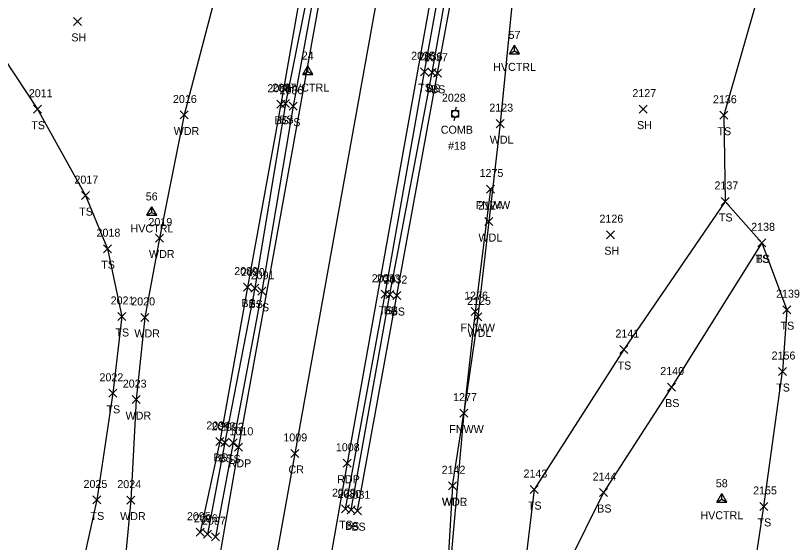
# Model space of a CAD drawing. Extents: x 1754529 to 1755810, y 621660 to 624656.
# Drawn here: x 1755421.2 to 1755616, y 623791.7 to 623923.4 of the extents above; entities that cross this region are included whole.
import ezdxf

# ---------------------------------------------------------------- set-up
doc = ezdxf.new("R2010")
doc.units = 0
for name, color, linetype in [('C_A', 7, 'Continuous'), ('C_I', 7, 'Continuous'), ('CPSM', 7, 'Continuous'), ('L_A', 7, 'Continuous'), ('L_I', 7, 'Continuous'), ('L_TIC', 7, 'Continuous'), ('LAWA', 7, 'Continuous'), ('LELB', 7, 'Continuous'), ('Level 14', 7, 'Continuous'), ('LFNC', 7, 'Continuous'), ('P_A', 7, 'Continuous'), ('P_I', 7, 'Continuous'), ('PET', 7, 'Continuous'), ('PRC', 7, 'Continuous'), ('U_A', 7, 'Continuous'), ('U_C', 7, 'Continuous'), ('U_I', 7, 'Continuous'), ('UP', 7, 'Continuous')]:
    doc.layers.add(name, color=color, linetype=linetype)

msp = doc.modelspace()

# ---------------------------------------------------------------- linework, layer by layer
at = {"layer": 'CPSM'}
for p, q in [((1755544.56, 623913.82), (1755545.81, 623915.99)), ((1755544.56, 623913.82), (1755545.81, 623914.54)), ((1755547.06, 623913.82), (1755545.81, 623915.99)), ((1755545.81, 623914.54), (1755545.81, 623915.99)), ((1755545.81, 623914.54), (1755545.81, 623914.54)), ((1755545.81, 623914.54), (1755547.06, 623913.82)), ((1755544.56, 623913.82), (1755547.06, 623913.82)), ((1755492.9, 623908.64), (1755494.15, 623910.8)), ((1755495.4, 623908.64), (1755494.15, 623910.8)), ((1755494.15, 623909.36), (1755494.15, 623910.8)), ((1755492.9, 623908.64), (1755494.15, 623909.36)), ((1755492.9, 623908.64), (1755495.4, 623908.64)), ((1755494.15, 623909.36), (1755494.15, 623909.36)), ((1755494.15, 623909.36), (1755495.4, 623908.64)), ((1755453.95, 623873.44), (1755455.2, 623875.6)), ((1755456.45, 623873.44), (1755455.2, 623875.6)), ((1755455.2, 623874.16), (1755455.2, 623875.6)), ((1755453.95, 623873.44), (1755455.2, 623874.16)), ((1755453.95, 623873.44), (1755456.45, 623873.44)), ((1755455.2, 623874.16), (1755455.2, 623874.16)), ((1755455.2, 623874.16), (1755456.45, 623873.44)), ((1755596.36, 623801.75), (1755597.61, 623803.92)), ((1755598.86, 623801.75), (1755597.61, 623803.92)), ((1755597.61, 623802.48), (1755597.61, 623803.92)), ((1755596.36, 623801.75), (1755597.61, 623802.48)), ((1755596.36, 623801.75), (1755598.86, 623801.75)), ((1755597.61, 623802.48), (1755597.61, 623802.48)), ((1755597.61, 623802.48), (1755598.86, 623801.75))]:
    msp.add_line(p, q, dxfattribs=at)
at = {"layer": 'L_TIC'}
for points in [[(1755435.6, 623920.91), (1755437.6, 623922.91)], [(1755437.6, 623920.91), (1755435.6, 623922.91)], [(1755522.35, 623908.32), (1755524.35, 623910.32)], [(1755524.35, 623908.32), (1755522.35, 623910.32)], [(1755524.28, 623908.17), (1755526.28, 623910.17)], [(1755526.28, 623908.17), (1755524.28, 623910.17)], [(1755525.55, 623907.94), (1755527.55, 623909.94)], [(1755527.55, 623907.94), (1755525.55, 623909.94)], [(1755425.67, 623898.96), (1755427.67, 623900.96)], [(1755427.67, 623898.96), (1755425.67, 623900.96)], [(1755486.4, 623900.21), (1755488.4, 623902.21)], [(1755488.4, 623900.21), (1755486.4, 623902.21)], [(1755487.64, 623900.37), (1755489.64, 623902.37)], [(1755489.64, 623900.37), (1755487.64, 623902.37)], [(1755489.5, 623899.71), (1755491.5, 623901.71)], [(1755491.5, 623899.71), (1755489.5, 623901.71)], [(1755576.98, 623898.98), (1755578.98, 623900.98)], [(1755578.98, 623898.98), (1755576.98, 623900.98)], [(1755462.31, 623897.52), (1755464.31, 623899.52)], [(1755464.31, 623897.52), (1755462.31, 623899.52)], [(1755597.16, 623897.45), (1755599.16, 623899.45)], [(1755599.16, 623897.45), (1755597.16, 623899.45)], [(1755541.23, 623895.35), (1755543.23, 623897.35)], [(1755543.23, 623895.35), (1755541.23, 623897.35)], [(1755437.63, 623877.37), (1755439.63, 623879.37)], [(1755439.63, 623877.37), (1755437.63, 623879.37)], [(1755538.8, 623879.02), (1755540.8, 623881.02)], [(1755540.8, 623879.02), (1755538.8, 623881.02)], [(1755597.5, 623875.91), (1755599.5, 623877.91)], [(1755599.5, 623875.91), (1755597.5, 623877.91)], [(1755597.5, 623875.91), (1755599.5, 623877.91)], [(1755599.5, 623875.91), (1755597.5, 623877.91)], [(1755538.41, 623870.88), (1755540.41, 623872.88)], [(1755540.41, 623870.88), (1755538.41, 623872.88)], [(1755568.81, 623867.6), (1755570.81, 623869.6)], [(1755570.81, 623867.6), (1755568.81, 623869.6)], [(1755456.13, 623866.77), (1755458.13, 623868.77)], [(1755458.13, 623866.77), (1755456.13, 623868.77)], [(1755606.67, 623865.57), (1755608.67, 623867.57)], [(1755608.67, 623865.57), (1755606.67, 623867.57)], [(1755606.67, 623865.57), (1755608.67, 623867.57)], [(1755608.67, 623865.57), (1755606.67, 623867.57)], [(1755443.15, 623864.1), (1755445.15, 623866.1)], [(1755445.15, 623864.1), (1755443.15, 623866.1)], [(1755478.14, 623854.5), (1755480.14, 623856.5)], [(1755480.14, 623854.5), (1755478.14, 623856.5)], [(1755479.93, 623854.25), (1755481.93, 623856.25)], [(1755481.93, 623854.25), (1755479.93, 623856.25)], [(1755481.67, 623853.46), (1755483.67, 623855.46)], [(1755483.67, 623853.46), (1755481.67, 623855.46)], [(1755512.5, 623852.71), (1755514.5, 623854.71)], [(1755514.5, 623852.71), (1755512.5, 623854.71)], [(1755513.71, 623852.68), (1755515.71, 623854.68)], [(1755515.71, 623852.68), (1755513.71, 623854.68)], [(1755515.45, 623852.4), (1755517.45, 623854.4)], [(1755517.45, 623852.4), (1755515.45, 623854.4)], [(1755535, 623848.38), (1755537, 623850.38)], [(1755537, 623848.38), (1755535, 623850.38)], [(1755612.91, 623848.85), (1755614.91, 623850.85)], [(1755614.91, 623848.85), (1755612.91, 623850.85)], [(1755446.69, 623847.16), (1755448.69, 623849.16)], [(1755448.69, 623847.16), (1755446.69, 623849.16)], [(1755452.48, 623846.93), (1755454.48, 623848.93)], [(1755454.48, 623846.93), (1755452.48, 623848.93)], [(1755535.68, 623847.06), (1755537.68, 623849.06)], [(1755537.68, 623847.06), (1755535.68, 623849.06)], [(1755572.19, 623838.9), (1755574.19, 623840.9)], [(1755574.19, 623838.9), (1755572.19, 623840.9)], [(1755611.83, 623833.4), (1755613.83, 623835.4)], [(1755613.83, 623833.4), (1755611.83, 623835.4)], [(1755611.83, 623833.4), (1755613.83, 623835.4)], [(1755613.83, 623833.4), (1755611.83, 623835.4)], [(1755584.04, 623829.52), (1755586.04, 623831.52)], [(1755586.04, 623829.52), (1755584.04, 623831.52)], [(1755444.46, 623827.96), (1755446.46, 623829.96)], [(1755446.46, 623827.96), (1755444.46, 623829.96)], [(1755450.28, 623826.38), (1755452.28, 623828.38)], [(1755452.28, 623826.38), (1755450.28, 623828.38)], [(1755532.19, 623823), (1755534.19, 623825)], [(1755534.19, 623823), (1755532.19, 623825)], [(1755471.16, 623815.92), (1755473.16, 623817.92)], [(1755473.16, 623815.92), (1755471.16, 623817.92)], [(1755472.47, 623815.7), (1755474.47, 623817.7)], [(1755474.47, 623815.7), (1755472.47, 623817.7)], [(1755474.56, 623815.58), (1755476.56, 623817.58)], [(1755476.56, 623815.58), (1755474.56, 623817.58)], [(1755529.31, 623804.85), (1755531.31, 623806.85)], [(1755531.31, 623804.85), (1755529.31, 623806.85)], [(1755529.31, 623804.85), (1755531.31, 623806.85)], [(1755531.31, 623804.85), (1755529.31, 623806.85)], [(1755549.78, 623803.9), (1755551.78, 623805.9)], [(1755551.78, 623803.9), (1755549.78, 623805.9)], [(1755567.05, 623803.16), (1755569.05, 623805.16)], [(1755569.05, 623803.16), (1755567.05, 623805.16)], [(1755440.47, 623801.31), (1755442.47, 623803.31)], [(1755442.47, 623801.31), (1755440.47, 623803.31)], [(1755448.92, 623801.26), (1755450.92, 623803.26)], [(1755450.92, 623801.26), (1755448.92, 623803.26)], [(1755607.16, 623799.69), (1755609.16, 623801.69)], [(1755609.16, 623799.69), (1755607.16, 623801.69)], [(1755502.59, 623799.12), (1755504.59, 623801.12)], [(1755504.59, 623799.12), (1755502.59, 623801.12)], [(1755504.03, 623798.81), (1755506.03, 623800.81)], [(1755506.03, 623798.81), (1755504.03, 623800.81)], [(1755505.63, 623798.61), (1755507.63, 623800.61)], [(1755507.63, 623798.61), (1755505.63, 623800.61)], [(1755466.3, 623793.24), (1755468.3, 623795.24)], [(1755468.3, 623793.24), (1755466.3, 623795.24)], [(1755468.09, 623792.73), (1755470.09, 623794.73)], [(1755470.09, 623792.73), (1755468.09, 623794.73)], [(1755470.08, 623792.12), (1755472.08, 623794.12)], [(1755472.08, 623792.12), (1755470.08, 623794.12)]]:
    msp.add_lwpolyline(points, dxfattribs=at)
at = {"layer": 'LAWA'}
for points in [[(1755302.36, 624324.44), (1755304.56, 624259.61), (1755306.26, 624221.06), (1755317.77, 624175.11), (1755335.71, 624145.2), (1755381.51, 624131.11), (1755414.09, 624129.63), (1755447.66, 624121.7), (1755477.75, 624119.95), (1755506.85, 624141.45), (1755530.35, 624173.06), (1755521.71, 624132.68), (1755513.72, 624106.64), (1755499.73, 624051.71), (1755491.49, 624010.7), (1755483.31, 623982.28), (1755477.84, 623954.98), (1755471.72, 623930.68), (1755463.31, 623898.52), (1755457.13, 623867.77), (1755453.48, 623847.93), (1755451.28, 623827.38), (1755449.92, 623802.26), (1755447.47, 623775.96)], [(1755611.46, 624290.08), (1755604.25, 624255.82), (1755602.4, 624225.76), (1755589.62, 624209.18), (1755583.3, 624161.08), (1755576.77, 624124.71), (1755568, 624075.88), (1755556.51, 624023.02), (1755550.67, 623972.84), (1755545.94, 623933.51), (1755542.23, 623896.35), (1755539.41, 623871.88), (1755536.68, 623848.06)], [(1755536.68, 623848.06), (1755533.19, 623824)], [(1755530.31, 623805.85), (1755533.19, 623824)], [(1755530.31, 623805.85), (1755527.62, 623759.58)]]:
    msp.add_lwpolyline(points, dxfattribs=at)
at = {"layer": 'LELB'}
for points in [[(1755564.22, 624305.05), (1755554.36, 624254.73), (1755544.82, 624207.63), (1755534.93, 624160.24), (1755525.26, 624110.43), (1755515.97, 624060.22), (1755506.84, 624008.91), (1755495.69, 623948.15), (1755487.4, 623901.21), (1755479.14, 623855.5), (1755472.16, 623816.92), (1755467.3, 623794.24)], [(1755566.56, 624304.36), (1755555.78, 624254.28), (1755546.32, 624207.47), (1755536.63, 624160.1), (1755526.96, 624110.16), (1755517.91, 624059.57), (1755508.44, 624008.83), (1755498, 623948.21), (1755488.64, 623901.37), (1755480.93, 623855.25), (1755473.47, 623816.7), (1755469.09, 623793.73)], [(1755569.13, 624303.44), (1755557.49, 624253.71), (1755548.32, 624207.42), (1755537.91, 624159.58), (1755529.76, 624109.95), (1755519.9, 624059.12), (1755510.42, 624008.64), (1755499.16, 623947.88), (1755490.5, 623900.71), (1755482.67, 623854.46), (1755475.56, 623816.58), (1755471.08, 623793.12)], [(1755503.59, 623800.12), (1755513.5, 623853.71), (1755523.35, 623909.32), (1755532.32, 623959.16), (1755541.82, 624011.12), (1755549.93, 624056.68), (1755559.84, 624109.07), (1755568.22, 624149.47), (1755576.95, 624193.92), (1755586.25, 624237.06), (1755598.86, 624293.76)], [(1755505.03, 623799.81), (1755514.71, 623853.68), (1755525.28, 623909.17), (1755534.08, 623958.86), (1755543.64, 624010.85), (1755551.62, 624056.17), (1755561.79, 624108.88), (1755569.47, 624149.58), (1755577.75, 624193.77), (1755587.59, 624237.08), (1755601.72, 624293.11)], [(1755506.63, 623799.61), (1755516.45, 623853.4), (1755526.55, 623908.94), (1755535.77, 623958.34), (1755544.53, 624010.84), (1755554.4, 624055.49), (1755562.72, 624108.68), (1755571.46, 624149.1), (1755579.12, 624193.4), (1755588.79, 624236.83), (1755601.72, 624293.11)], [(1755642.06, 624060.86), (1755634.66, 624026.67), (1755623.28, 624004), (1755620.94, 623965.19), (1755618.71, 623952.2), (1755606.81, 623928.84), (1755598.16, 623898.45), (1755598.5, 623876.91), (1755607.67, 623866.57), (1755613.91, 623849.85), (1755612.83, 623834.4)], [(1755412.5, 623921.31), (1755426.67, 623899.96), (1755438.63, 623878.37), (1755444.15, 623865.1), (1755447.69, 623848.16), (1755445.46, 623828.96), (1755441.47, 623802.31), (1755434.62, 623771.42)], [(1755598.5, 623876.91), (1755573.19, 623839.9), (1755550.78, 623804.9), (1755547.96, 623782.07), (1755527.62, 623759.58), (1755529.98, 623748.49), (1755534.1, 623738.68), (1755572.84, 623724.08), (1755585.86, 623719.5), (1755600.61, 623741.43), (1755603.92, 623772.48), (1755608.16, 623800.69), (1755612.83, 623834.4)], [(1755607.67, 623866.57), (1755585.04, 623830.52), (1755568.05, 623804.16), (1755554.59, 623776.92), (1755529.98, 623748.49)]]:
    msp.add_lwpolyline(points, dxfattribs=at)
at = {"layer": 'Level 14'}
for points in [[(1755475.9, 623814.46), (1755477.9, 623816.46)], [(1755477.9, 623814.46), (1755475.9, 623816.46)], [(1755489.93, 623812.93), (1755491.93, 623814.93)], [(1755491.93, 623812.93), (1755489.93, 623814.93)], [(1755503.04, 623810.48), (1755505.04, 623812.48)], [(1755505.04, 623810.48), (1755503.04, 623812.48)]]:
    msp.add_lwpolyline(points, dxfattribs=at)
at = {"layer": 'LFNC'}
msp.add_lwpolyline([(1755539.8, 623880.02), (1755536, 623849.38), (1755533.19, 623824), (1755528.55, 623772.58)], dxfattribs=at)
at = {"layer": 'PET'}
for points in [[(1755535.07, 624132.59), (1755507.27, 623983.72), (1755476.9, 623815.46), (1755460.3, 623719.87), (1755437.79, 623591.8), (1755421.36, 623504.45), (1755418.26, 623495.73), (1755404.2, 623424.5), (1755397.43, 623386.49), (1755390.98, 623344.71), (1755391.72, 623340.77), (1755385.02, 623296.56), (1755379.33, 623252.08), (1755376.53, 623216.25), (1755375.95, 623174.43), (1755377.19, 623132.58)], [(1755561.91, 624125.77), (1755533.66, 623976.91), (1755504.04, 623811.48), (1755486.8, 623713.65), (1755464.22, 623587.1), (1755446.31, 623490.47), (1755433.28, 623420.6), (1755425.75, 623380.35), (1755417.64, 623332.29), (1755411.38, 623292.51), (1755405.94, 623251.45), (1755403.49, 623215.07), (1755403.14, 623175.05), (1755404.1, 623131.29)]]:
    msp.add_lwpolyline(points, dxfattribs=at)
at = {"layer": 'PRC'}
msp.add_lwpolyline([(1755548.82, 624129.6), (1755520.89, 623980.45), (1755490.93, 623813.93), (1755473.47, 623716.78), (1755450.77, 623588.43), (1755432.8, 623492.49), (1755420.05, 623422.21), (1755412.93, 623383.28), (1755404.64, 623333.82), (1755398.35, 623294.75), (1755393.11, 623251.83), (1755390.3, 623215.98), (1755389.28, 623175.01), (1755390.29, 623132.74)], dxfattribs=at)
at = {"layer": 'UP'}
for p, q in [((1755530.2, 623898.01), (1755530.2, 623899.68)), ((1755530.2, 623899.68), (1755531.86, 623899.68)), ((1755531.28, 623900.51), (1755531.03, 623899.68)), ((1755531.03, 623898.84), (1755531.03, 623898.84)), ((1755531.86, 623899.68), (1755531.86, 623898.01)), ((1755531.86, 623898.01), (1755530.2, 623898.01)), ((1755530.78, 623897.18), (1755531.03, 623898.01))]:
    msp.add_line(p, q, dxfattribs=at)
msp.add_circle((1755531.03, 623898.84), 0.833, dxfattribs=at)

# ---------------------------------------------------------------- texts
at = {"layer": 'C_A'}
for p in [(1755540.5, 623909.54), (1755488.84, 623904.36), (1755449.89, 623869.16), (1755592.3, 623797.48)]:
    msp.add_text('HVCTRL', height=2, dxfattribs=at).set_placement(p)
at = {"layer": 'C_I'}
for s, p in [('57', (1755544.35, 623917.54)), ('24', (1755492.68, 623912.36)), ('56', (1755453.68, 623877.16)), ('58', (1755596.14, 623805.48))]:
    msp.add_text(s, height=2, dxfattribs=at).set_placement(p)
at = {"layer": 'L_A'}
for s, p in [('SH', (1755435.08, 623916.91)), ('TS', (1755521.76, 623904.32)), ('BS', (1755523.72, 623904.17)), ('BS', (1755524.99, 623903.94)), ('TS', (1755425.08, 623894.96)), ('BS', (1755485.85, 623896.21)), ('BS', (1755487.08, 623896.37)), ('TS', (1755488.91, 623895.71)), ('SH', (1755576.47, 623894.98)), ('WDR', (1755460.67, 623893.52)), ('TS', (1755596.57, 623893.45)), ('WDL', (1755539.65, 623891.35)), ('TS', (1755437.04, 623873.37)), ('FNWW', (1755536.14, 623875.02)), ('TS', (1755596.91, 623871.91)), ('TS', (1755596.91, 623871.91)), ('WDL', (1755536.83, 623866.88)), ('SH', (1755568.29, 623863.6)), ('WDR', (1755454.49, 623862.77)), ('TS', (1755606.08, 623861.57)), ('BS', (1755606.11, 623861.57)), ('TS', (1755442.56, 623860.1)), ('BS', (1755477.58, 623850.5)), ('BS', (1755479.37, 623850.25)), ('TS', (1755481.08, 623849.46)), ('TS', (1755511.91, 623848.71)), ('BS', (1755513.15, 623848.68)), ('BS', (1755514.89, 623848.4)), ('FNWW', (1755532.34, 623844.38)), ('TS', (1755612.32, 623844.85)), ('TS', (1755446.1, 623843.16)), ('WDR', (1755450.84, 623842.93)), ('WDL', (1755534.1, 623843.06)), ('TS', (1755571.6, 623834.9)), ('TS', (1755611.24, 623829.4)), ('TS', (1755611.24, 623829.4)), ('BS', (1755583.48, 623825.52)), ('TS', (1755443.87, 623823.96)), ('WDR', (1755448.64, 623822.38)), ('FNWW', (1755529.53, 623819)), ('BS', (1755470.6, 623811.92)), ('BS', (1755471.91, 623811.7)), ('TS', (1755473.97, 623811.58)), ('WDR', (1755527.67, 623800.85)), ('WDL', (1755527.73, 623800.85)), ('TS', (1755549.19, 623799.9)), ('TS', (1755439.88, 623797.31)), ('BS', (1755566.5, 623799.16)), ('WDR', (1755447.28, 623797.26)), ('TS', (1755606.57, 623795.69)), ('TS', (1755502, 623795.12)), ('BS', (1755503.47, 623794.81)), ('BS', (1755505.07, 623794.61))]:
    msp.add_text(s, height=2, dxfattribs=at).set_placement(p)
at = {"layer": 'L_I'}
for s, p in [('2035', (1755520.01, 623912.32)), ('2036', (1755521.89, 623912.17)), ('2037', (1755523.21, 623911.94)), ('2011', (1755424.46, 623902.96)), ('2088', (1755484.07, 623904.21)), ('2087', (1755485.3, 623904.37)), ('2086', (1755487.11, 623903.71)), ('2127', (1755575.29, 623902.98)), ('2016', (1755460.48, 623901.52)), ('2136', (1755595.42, 623901.45)), ('2123', (1755539.54, 623899.35)), ('1275', (1755537.1, 623883.02)), ('2017', (1755435.86, 623881.37)), ('2137', (1755595.81, 623879.91)), ('2137', (1755595.81, 623879.91)), ('2124', (1755536.71, 623874.88)), ('2126', (1755567.06, 623871.6)), ('2019', (1755454.35, 623870.77)), ('2138', (1755604.98, 623869.57)), ('2138', (1755604.98, 623869.57)), ('2018', (1755441.38, 623868.1)), ('2089', (1755475.79, 623858.5)), ('2090', (1755477.5, 623858.25)), ('2091', (1755479.9, 623857.46)), ('2034', (1755510.16, 623856.71)), ('2033', (1755511.37, 623856.68)), ('2032', (1755513.11, 623856.4)), ('1276', (1755533.25, 623852.38)), ('2139', (1755611.21, 623852.85)), ('2021', (1755444.91, 623851.16)), ('2020', (1755450.06, 623850.93)), ('2125', (1755533.99, 623851.06)), ('2141', (1755571.06, 623842.9)), ('2156', (1755610.08, 623837.4)), ('2156', (1755610.08, 623837.4)), ('2140', (1755582.26, 623833.52)), ('2022', (1755442.12, 623831.96)), ('2023', (1755447.94, 623830.38)), ('1277', (1755530.49, 623827)), ('2094', (1755468.82, 623819.92)), ('2093', (1755470.13, 623819.7)), ('2092', (1755472.23, 623819.58)), ('2142', (1755527.62, 623808.85)), ('2142', (1755527.62, 623808.85)), ('2143', (1755548.09, 623807.9)), ('2144', (1755565.36, 623807.16)), ('2025', (1755438.13, 623805.31)), ('2024', (1755446.58, 623805.26)), ('2029', (1755500.24, 623803.12)), ('2155', (1755605.47, 623803.69)), ('2030', (1755501.6, 623802.81)), ('2031', (1755503.86, 623802.61)), ('2095', (1755463.97, 623797.24)), ('2096', (1755465.7, 623796.73)), ('2097', (1755467.74, 623796.12))]:
    msp.add_text(s, height=2, dxfattribs=at).set_placement(p)
at = {"layer": 'P_A'}
for s, p in [('RDP', (1755474.39, 623810.46)), ('CR', (1755489.36, 623808.93)), ('RDP', (1755501.53, 623806.48))]:
    msp.add_text(s, height=2, dxfattribs=at).set_placement(p)
at = {"layer": 'P_I'}
for s, p in [('1010', (1755474.61, 623818.46)), ('1009', (1755488.07, 623816.93)), ('1008', (1755501.19, 623814.48))]:
    msp.add_text(s, height=2, dxfattribs=at).set_placement(p)
at = {"layer": 'U_A'}
msp.add_text('COMB', height=2, dxfattribs=at).set_placement((1755527.41, 623893.84))
at = {"layer": 'U_C'}
msp.add_text('#18', height=2, dxfattribs=at).set_placement((1755529.23, 623889.84))
at = {"layer": 'U_I'}
msp.add_text('2028', height=2, dxfattribs=at).set_placement((1755527.69, 623901.84))

doc.saveas('drawing.dxf')
